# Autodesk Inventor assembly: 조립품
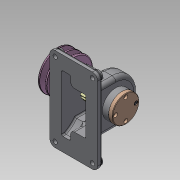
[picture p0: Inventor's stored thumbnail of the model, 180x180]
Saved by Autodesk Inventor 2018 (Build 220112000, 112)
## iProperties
Created: 2024-01
Part Number: 조립품
Material: 일반
Document SubType Name: Assembly
Designer: home
Author: home
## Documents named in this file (16)
- C:\Users\home\Desktop\740104V1006\조립품.iam
- C:\Users\home\Desktop\740104V1006\본체.ipt
- C:\Users\home\Desktop\740104V1006\V-벨트 풀리.ipt
- C:\Users\home\Desktop\740104V1006\깊은 홈 볼 베어링 6202.ipt
- C:\Users\home\Desktop\740104V1006\뒷커버.ipt
- C:\Users\home\Desktop\740104V1006\스퍼 기어.ipt
- C:\Users\home\Desktop\740104V1006\앞커버.ipt
- C:\Users\home\Desktop\740104V1006\엔드 캡.ipt
- C:\Users\home\Desktop\740104V1006\오일 실 15 25 7.ipt
- C:\Users\home\Desktop\740104V1006\육각 소켓 머리 볼트 M4 x 12.ipt
- C:\Users\home\Desktop\740104V1006\축.ipt
- C:\Users\home\Desktop\740104V1006\평와셔 M4.ipt
- C:\Users\home\Desktop\740104V1006\평행 키 3x3x12.ipt
- C:\Users\home\Desktop\740104V1006\평행 키 5x5x32.ipt
- C:\Users\home\Desktop\740104V1006\칼라.ipt
- C:\Users\home\Desktop\740104V1006\육각 머리 볼트 M4 x 12.ipt
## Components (1 placed, 1 different names)
1. V-벨트 풀리:1
